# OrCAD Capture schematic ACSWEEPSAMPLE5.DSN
size A
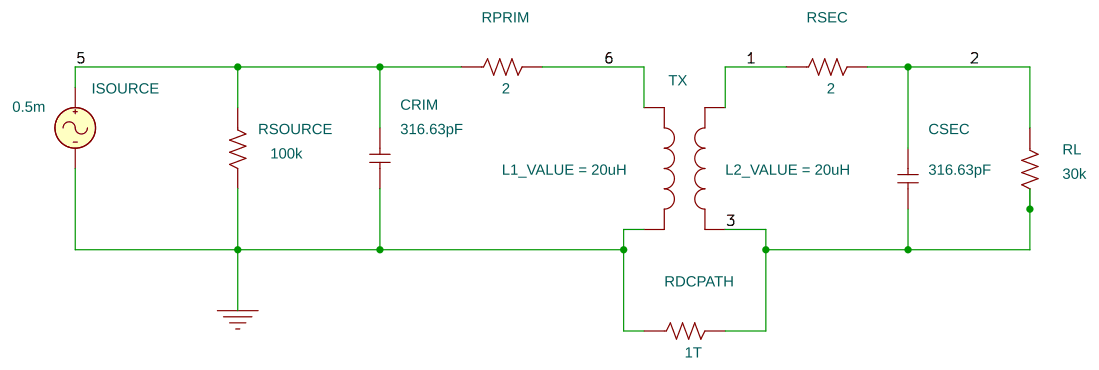
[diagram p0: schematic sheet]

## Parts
CRIM  316.63pF  [RAD/CK05]
CSEC  316.63pF  [RAD/CK05]
ISOURCE  IAC
RDCPATH  1T  [AX/RC05]
RL  30k  [AX/RC05]
RPRIM  2  [AX/RC05]
RSEC  2  [AX/RC05]
RSOURCE  100k  [AX/RC05]
TX  XFRM_LINEAR

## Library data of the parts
CRIM CSEC = C
ISOURCE = IAC: ACMAG: 0.5m
RDCPATH RL RPRIM RSEC RSOURCE = R
TX = XFRM_LINEAR: COUPLING: .1; L1_VALUE: 20uH; L2_VALUE: 20uH

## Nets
0: CRIM.2 ISOURCE.2(-) RDCPATH.1 RSOURCE.2 TX.2
1: RSEC.1 TX.3
2: CSEC.1 RL.1 RSEC.2
3: CSEC.2 RDCPATH.2 RL.2 TX.4
5: CRIM.1 ISOURCE.1(+) RPRIM.1 RSOURCE.1
6: RPRIM.2 TX.1
